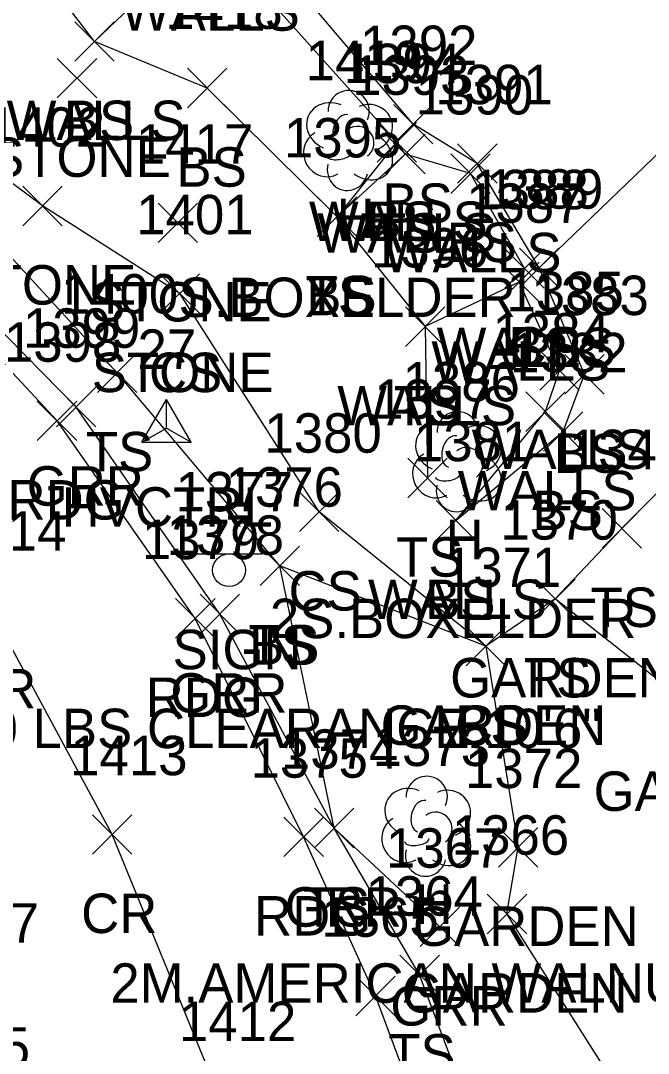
# Model space of a CAD drawing. Extents: x 1459992 to 1461532, y 647785 to 648535.
# Drawn here: x 1461373.7 to 1461405.5, y 648118.2 to 648170.5 of the extents above; entities that cross this region are included whole.
import ezdxf

# ---------------------------------------------------------------- set-up
doc = ezdxf.new("R2010")
doc.units = 0
for name, color, linetype in [('C_A', 7, 'Continuous'), ('C_I', 7, 'Continuous'), ('CPSM', 7, 'Continuous'), ('L_A', 7, 'Continuous'), ('L_C', 7, 'Continuous'), ('L_I', 7, 'Continuous'), ('L_TIC', 7, 'Continuous'), ('LAPB', 7, 'Continuous'), ('LASF', 7, 'Continuous'), ('LELB', 7, 'Continuous'), ('LTD', 7, 'Continuous'), ('LWS', 7, 'Continuous'), ('P_A', 7, 'Continuous'), ('P_I', 7, 'Continuous'), ('P_TIC', 7, 'Continuous'), ('PEU', 7, 'Continuous'), ('PRC', 7, 'Continuous'), ('R_A', 7, 'Continuous'), ('R_I', 7, 'Continuous'), ('R_TIC', 7, 'Continuous'), ('RGR', 7, 'Continuous'), ('S_A', 7, 'Continuous'), ('S_C', 7, 'Continuous'), ('S_I', 7, 'Continuous'), ('SSGN', 7, 'Continuous')]:
    doc.layers.add(name, color=color, linetype=linetype)

msp = doc.modelspace()

# ---------------------------------------------------------------- linework, layer by layer
at = {"layer": 'CPSM'}
for p, q in [((1461379.852, 648149.141), (1461381.102, 648151.306)), ((1461382.352, 648149.141), (1461381.102, 648151.306)), ((1461381.102, 648149.863), (1461381.102, 648151.306)), ((1461379.852, 648149.141), (1461381.102, 648149.863)), ((1461381.102, 648149.863), (1461381.102, 648149.863)), ((1461381.102, 648149.863), (1461382.352, 648149.141)), ((1461379.852, 648149.141), (1461382.352, 648149.141))]:
    msp.add_line(p, q, dxfattribs=at)
at = {"layer": 'L_TIC'}
for points in [[(1461376.464, 648168.459), (1461378.464, 648170.459)], [(1461378.464, 648168.459), (1461376.464, 648170.459)], [(1461376.464, 648168.459), (1461378.464, 648170.459)], [(1461378.464, 648168.459), (1461376.464, 648170.459)], [(1461375.571, 648166.594), (1461377.571, 648168.594)], [(1461377.571, 648166.594), (1461375.571, 648168.594)], [(1461382.172, 648166.096), (1461384.172, 648168.096)], [(1461384.172, 648166.096), (1461382.172, 648168.096)], [(1461392.612, 648164.262), (1461394.612, 648166.262)], [(1461394.612, 648164.262), (1461392.612, 648166.262)], [(1461391.781, 648163.345), (1461393.781, 648165.345)], [(1461393.781, 648163.345), (1461391.781, 648165.345)], [(1461391.781, 648163.345), (1461393.781, 648165.345)], [(1461393.781, 648163.345), (1461391.781, 648165.345)], [(1461392.211, 648162.751), (1461394.211, 648164.751)], [(1461394.211, 648162.751), (1461392.211, 648164.751)], [(1461392.211, 648162.751), (1461394.211, 648164.751)], [(1461394.211, 648162.751), (1461392.211, 648164.751)], [(1461395.519, 648161.757), (1461397.519, 648163.757)], [(1461397.519, 648161.757), (1461395.519, 648163.757)], [(1461395.861, 648162.276), (1461397.861, 648164.276)], [(1461397.861, 648162.276), (1461395.861, 648164.276)], [(1461373.821, 648160.121), (1461375.821, 648162.121)], [(1461375.821, 648160.121), (1461373.821, 648162.121)], [(1461380.683, 648159.265), (1461382.683, 648161.265)], [(1461382.683, 648159.265), (1461380.683, 648161.265)], [(1461388.751, 648159.577), (1461390.751, 648161.577)], [(1461390.751, 648159.577), (1461388.751, 648161.577)], [(1461388.751, 648159.577), (1461390.751, 648161.577)], [(1461390.751, 648159.577), (1461388.751, 648161.577)], [(1461398.256, 648156.952), (1461400.256, 648158.952)], [(1461400.256, 648156.952), (1461398.256, 648158.952)], [(1461399, 648156.981), (1461401, 648158.981)], [(1461401, 648156.981), (1461399, 648158.981)], [(1461399, 648156.981), (1461401, 648158.981)], [(1461401, 648156.981), (1461399, 648158.981)], [(1461397.988, 648156.264), (1461399.988, 648158.264)], [(1461399.988, 648156.264), (1461397.988, 648158.264)], [(1461397.988, 648156.264), (1461399.988, 648158.264)], [(1461399.988, 648156.264), (1461397.988, 648158.264)], [(1461380.779, 648155.684), (1461382.779, 648157.684)], [(1461382.779, 648155.684), (1461380.779, 648157.684)], [(1461380.779, 648155.684), (1461382.779, 648157.684)], [(1461382.779, 648155.684), (1461380.779, 648157.684)], [(1461380.779, 648155.684), (1461382.779, 648157.684)], [(1461382.779, 648155.684), (1461380.779, 648157.684)], [(1461393.218, 648154.003), (1461395.218, 648156.003)], [(1461395.218, 648154.003), (1461393.218, 648156.003)], [(1461393.218, 648154.003), (1461395.218, 648156.003)], [(1461395.218, 648154.003), (1461393.218, 648156.003)], [(1461377.611, 648151.668), (1461379.611, 648153.668)], [(1461379.611, 648151.668), (1461377.611, 648153.668)], [(1461400.031, 648151.786), (1461402.031, 648153.786)], [(1461402.031, 648151.786), (1461400.031, 648153.786)], [(1461401.296, 648151.589), (1461403.296, 648153.589)], [(1461403.296, 648151.589), (1461401.296, 648153.589)], [(1461399.322, 648149.694), (1461401.322, 648151.694)], [(1461401.322, 648149.694), (1461399.322, 648151.694)], [(1461400.217, 648148.693), (1461402.217, 648150.693)], [(1461402.217, 648148.693), (1461400.217, 648150.693)], [(1461393.334, 648146.331), (1461395.334, 648148.331)], [(1461395.334, 648146.331), (1461393.334, 648148.331)], [(1461387.851, 648144.613), (1461389.851, 648146.613)], [(1461389.851, 648144.613), (1461387.851, 648146.613)], [(1461394.776, 648144.183), (1461396.776, 648146.183)], [(1461396.776, 648144.183), (1461394.776, 648146.183)], [(1461394.776, 648144.183), (1461396.776, 648146.183)], [(1461396.776, 648144.183), (1461394.776, 648146.183)], [(1461403.189, 648143.779), (1461405.189, 648145.779)], [(1461405.189, 648143.779), (1461403.189, 648145.779)], [(1461385.85, 648141.876), (1461387.85, 648143.876)], [(1461387.85, 648141.876), (1461385.85, 648143.876)], [(1461385.85, 648141.876), (1461387.85, 648143.876)], [(1461387.85, 648141.876), (1461385.85, 648143.876)], [(1461399.813, 648140.208), (1461401.813, 648142.208)], [(1461401.813, 648140.208), (1461399.813, 648142.208)], [(1461399.813, 648140.208), (1461401.813, 648142.208)], [(1461401.813, 648140.208), (1461399.813, 648142.208)], [(1461396.294, 648137.804), (1461398.294, 648139.804)], [(1461398.294, 648137.804), (1461396.294, 648139.804)], [(1461396.294, 648137.804), (1461398.294, 648139.804)], [(1461398.294, 648137.804), (1461396.294, 648139.804)], [(1461396.294, 648137.804), (1461398.294, 648139.804)], [(1461398.294, 648137.804), (1461396.294, 648139.804)], [(1461388.604, 648128.591), (1461390.604, 648130.591)], [(1461390.604, 648128.591), (1461388.604, 648130.591)], [(1461397.931, 648127.614), (1461399.931, 648129.614)], [(1461399.931, 648127.614), (1461397.931, 648129.614)], [(1461397.931, 648127.614), (1461399.931, 648129.614)], [(1461399.931, 648127.614), (1461397.931, 648129.614)], [(1461397.363, 648124.235), (1461399.363, 648126.235)], [(1461399.363, 648124.235), (1461397.363, 648126.235)], [(1461392.938, 648121.147), (1461394.938, 648123.147)], [(1461394.938, 648121.147), (1461392.938, 648123.147)]]:
    msp.add_lwpolyline(points, dxfattribs=at)
at = {"layer": 'LAPB'}
for points in [[(1461407.924, 648110.162), (1461411.912, 648123.815), (1461408.084, 648135.457), (1461400.813, 648141.208), (1461397.294, 648138.804), (1461398.931, 648128.614)], [(1461407.924, 648110.162), (1461398.363, 648125.235), (1461398.931, 648128.614)]]:
    msp.add_lwpolyline(points, dxfattribs=at)
at = {"layer": 'LASF'}
msp.add_lwpolyline([(1461381.779, 648156.684), (1461374.821, 648161.121), (1461367.27, 648166.741), (1461364.684, 648166.619), (1461366.684, 648167.245)], dxfattribs=at)
at = {"layer": 'LELB'}
for points in [[(1461400, 648157.981), (1461410.206, 648167.796), (1461433.497, 648170.261), (1461450.015, 648174.465), (1461460.23, 648178.212), (1461481.957, 648192.378), (1461506.16, 648200.217)], [(1461395.776, 648145.183), (1461401.217, 648149.693), (1461402.296, 648152.589), (1461400, 648157.981), (1461396.861, 648163.276), (1461393.612, 648165.262), (1461384.114, 648176.457), (1461379.778, 648178.815), (1461366.22, 648181.937)], [(1461392.781, 648164.345), (1461389.751, 648160.577), (1461383.172, 648167.096), (1461377.464, 648169.459), (1461372.614, 648175.782)], [(1461437.839, 648100.682), (1461424.99, 648102.601), (1461410.253, 648104.75), (1461403.249, 648108.099), (1461397.824, 648111.829), (1461393.938, 648122.147), (1461389.604, 648129.591), (1461386.85, 648142.876), (1461378.611, 648152.668), (1461368.623, 648163.532), (1461366.902, 648163.443), (1461362.607, 648163.899), (1461362.17, 648163.299)], [(1461393.211, 648163.751), (1461389.751, 648160.577), (1461394.218, 648155.003), (1461394.334, 648147.331)], [(1461397.294, 648138.804), (1461388.851, 648145.613), (1461381.779, 648156.684)], [(1461411.698, 648152.367), (1461404.189, 648144.779), (1461400.813, 648141.208)], [(1461397.294, 648138.804), (1461386.85, 648142.876)]]:
    msp.add_lwpolyline(points, dxfattribs=at)
at = {"layer": 'LTD'}
for p, q in [((1461390.294, 648164.49), (1461390.294, 648164.49)), ((1461390.294, 648164.49), (1461390.294, 648164.49)), ((1461395.818, 648148.214), (1461395.818, 648148.214)), ((1461395.818, 648148.214), (1461395.818, 648148.214)), ((1461394.253, 648129.733), (1461394.253, 648129.733)), ((1461394.253, 648129.733), (1461394.253, 648129.733))]:
    msp.add_line(p, q, dxfattribs=at)
for centre in [(1461390.341, 648165.924), (1461395.865, 648149.648), (1461394.3, 648131.167)]:
    msp.add_arc(centre, 1.047, 335.5272, 180.9563, dxfattribs=at)
for centre, major_axis, ratio, start_param, end_param in [((1461389.502, 648165.157), (1.21, -0.512), 0.895232, 1.570796, 4.712389), ((1461391.335, 648165.074), (-1.141, -0.483), 0.949671, 1.570796, 4.712389), ((1461390.085, 648164.948), (-0.208, -0.792), 0.645439, 3.141593, 6.283185), ((1461389.211, 648163.782), (0.584, -1.042), 0.959034, 3.141593, 6.283185), ((1461390.794, 648164.323), (-0.5, 0.667), 0.989748, 3.141593, 6.283185), ((1461391.294, 648163.657), (-1.09, 0.792), 0.841452, 1.570796, 4.712389), ((1461389.836, 648163.74), (-0.625, -0.083), 0.423636, 0, 3.141593), ((1461390.294, 648162.99), (0.265, 1.061), 0.942809, 1.570796, 4.712389), ((1461395.026, 648148.881), (1.21, -0.512), 0.895232, 1.570796, 4.712389), ((1461396.86, 648148.798), (-1.141, -0.483), 0.949671, 1.570796, 4.712389), ((1461395.61, 648148.673), (-0.208, -0.792), 0.645439, 3.141593, 6.283185), ((1461396.318, 648148.048), (-0.5, 0.667), 0.989748, 3.141593, 6.283185), ((1461394.735, 648147.506), (0.584, -1.042), 0.959034, 3.141593, 6.283185), ((1461396.818, 648147.381), (-1.09, 0.792), 0.841452, 1.570796, 4.712389), ((1461395.36, 648147.464), (-0.625, -0.083), 0.423636, 0, 3.141593), ((1461395.818, 648146.714), (0.265, 1.061), 0.942809, 1.570796, 4.712389), ((1461393.461, 648130.399), (1.21, -0.512), 0.895232, 1.570796, 4.712389), ((1461395.294, 648130.316), (-1.141, -0.483), 0.949671, 1.570796, 4.712389), ((1461394.044, 648130.191), (-0.208, -0.792), 0.645439, 3.141593, 6.283185), ((1461394.753, 648129.566), (-0.5, 0.667), 0.989748, 3.141593, 6.283185), ((1461393.17, 648129.024), (0.584, -1.042), 0.959034, 3.141593, 6.283185), ((1461395.253, 648128.9), (-1.09, 0.792), 0.841452, 1.570796, 4.712389), ((1461393.795, 648128.983), (-0.625, -0.083), 0.423636, 0, 3.141593), ((1461394.253, 648128.233), (0.265, 1.061), 0.942809, 1.570796, 4.712389)]:
    msp.add_ellipse(centre, major_axis=major_axis, ratio=ratio, start_param=start_param, end_param=end_param, dxfattribs=at)
at = {"layer": 'LWS'}
for points in [[(1461395.776, 648145.183), (1461400.322, 648150.694), (1461401.031, 648152.786), (1461398.988, 648157.264), (1461399.256, 648157.952), (1461396.519, 648162.757), (1461393.211, 648163.751), (1461392.781, 648164.345), (1461383.255, 648175.001), (1461379.666, 648178.519), (1461366.22, 648181.937), (1461358.31, 648179.355), (1461359.375, 648177.485)], [(1461383.255, 648175.001), (1461377.464, 648169.459)], [(1461398.988, 648157.264), (1461394.218, 648155.003)]]:
    msp.add_lwpolyline(points, dxfattribs=at)
at = {"layer": 'P_TIC'}
for points in [[(1461374.562, 648149.224), (1461376.562, 648151.224)], [(1461376.562, 648149.224), (1461374.562, 648151.224)], [(1461381.567, 648139.218), (1461383.567, 648141.218)], [(1461383.567, 648139.218), (1461381.567, 648141.218)], [(1461377.351, 648128.267), (1461379.351, 648130.267)], [(1461379.351, 648128.267), (1461377.351, 648130.267)], [(1461387.059, 648128.141), (1461389.059, 648130.141)], [(1461389.059, 648128.141), (1461387.059, 648130.141)], [(1461390.697, 648120.078), (1461392.697, 648122.078)], [(1461392.697, 648120.078), (1461390.697, 648122.078)]]:
    msp.add_lwpolyline(points, dxfattribs=at)
at = {"layer": 'PEU'}
msp.add_lwpolyline([(1461405.272, 648031.274), (1461404.297, 648042.515), (1461403.915, 648074), (1461402.282, 648079.787), (1461395.979, 648109.613), (1461391.697, 648121.078), (1461388.059, 648129.141), (1461382.567, 648140.218), (1461375.562, 648150.224), (1461367.209, 648159.2), (1461362.17, 648163.299), (1461358.126, 648158.61), (1461353.744, 648153.756)], dxfattribs=at)
at = {"layer": 'PRC'}
msp.add_lwpolyline([(1461399.102, 647801.607), (1461400.203, 647838.194), (1461399.73, 647875.765), (1461399.539, 647898.401), (1461398.446, 647928.211), (1461395.012, 647961.974), (1461394.123, 647993.813), (1461392.15, 648024.041), (1461390.381, 648057.367), (1461388.518, 648080.662), (1461387.016, 648100.033), (1461383.866, 648115.79), (1461378.351, 648129.267), (1461372.213, 648140.65), (1461365.441, 648150.969), (1461358.126, 648158.61)], dxfattribs=at)
at = {"layer": 'R_TIC'}
for points in [[(1461375.533, 648149.93), (1461377.533, 648151.93)], [(1461377.533, 648149.93), (1461375.533, 648151.93)], [(1461382.809, 648139.436), (1461384.809, 648141.436)], [(1461384.809, 648139.436), (1461382.809, 648141.436)], [(1461388.604, 648128.591), (1461390.604, 648130.591)], [(1461390.604, 648128.591), (1461388.604, 648130.591)], [(1461393.966, 648123.578), (1461395.966, 648125.578)], [(1461395.966, 648123.578), (1461393.966, 648125.578)]]:
    msp.add_lwpolyline(points, dxfattribs=at)
at = {"layer": 'RGR'}
msp.add_lwpolyline([(1461394.966, 648124.578), (1461389.604, 648129.591), (1461383.809, 648140.436), (1461376.533, 648150.93), (1461367.825, 648159.773), (1461362.607, 648163.899)], dxfattribs=at)
at = {"layer": 'SSGN'}
for p, q in [((1461382.631, 648143.493), (1461385.964, 648143.493)), ((1461384.278, 648142.659), (1461384.278, 648142.659))]:
    msp.add_line(p, q, dxfattribs=at)
msp.add_circle((1461384.278, 648142.659), 0.833, dxfattribs=at)

# ---------------------------------------------------------------- texts
at = {"layer": 'C_A'}
msp.add_text('HVCTRL', height=2, dxfattribs=at).set_placement((1461375.795, 648144.863))
at = {"layer": 'C_I'}
msp.add_text('27', height=2, dxfattribs=at).set_placement((1461379.638, 648152.863))
at = {"layer": 'L_A'}
for s, p in [('WALLS', (1461378.798, 648170.001)), ('WALLS', (1461378.798, 648170.001)), ('WALLS', (1461373.007, 648164.459)), ('BS', (1461375.905, 648164.459)), ('STONE', (1461372.114, 648162.594)), ('BS', (1461381.612, 648162.096)), ('BS', (1461392.053, 648160.262)), ('WALLS', (1461388.324, 648159.345)), ('H', (1461389.727, 648159.49)), ('BS', (1461391.222, 648159.345)), ('WALLS', (1461388.754, 648158.751)), ('TS', (1461391.621, 648158.751)), ('BS', (1461395.302, 648158.276)), ('WALLS', (1461392.063, 648157.757)), ('STONE', (1461370.364, 648156.121)), ('TS', (1461388.161, 648155.577)), ('BS', (1461388.192, 648155.577)), ('STONE', (1461377.226, 648155.265)), ('WALLS', (1461394.8, 648152.952)), ('CS', (1461398.441, 648152.981)), ('BS', (1461398.441, 648152.981)), ('WALLS', (1461394.531, 648152.264)), ('WALLS', (1461394.531, 648152.264)), ('STONE', (1461377.322, 648151.684)), ('STONE', (1461377.322, 648151.684)), ('CS', (1461380.22, 648151.684)), ('WALLS', (1461389.761, 648150.003)), ('TS', (1461392.627, 648150.003)), ('TS', (1461377.02, 648147.668)), ('WALLS', (1461396.574, 648147.786)), ('BS', (1461400.736, 648147.589)), ('WALLS', (1461395.865, 648145.694)), ('BS', (1461399.658, 648144.693)), ('H', (1461395.251, 648143.214)), ('TS', (1461392.744, 648142.331)), ('CS', (1461387.292, 648140.613)), ('WALLS', (1461391.319, 648140.183)), ('BS', (1461394.217, 648140.183)), ('TS', (1461402.599, 648139.779)), ('TS', (1461385.259, 648137.876)), ('BS', (1461385.291, 648137.876)), ('GARDEN', (1461395.483, 648136.208)), ('TS', (1461399.223, 648136.208)), ('GARDEN', (1461391.963, 648133.804)), ('CS', (1461395.735, 648133.804)), ('BS', (1461395.735, 648133.804)), ('GARDEN', (1461402.754, 648130.457)), ('TS', (1461388.013, 648124.591)), ('H', (1461393.686, 648124.733)), ('GARDEN', (1461393.6, 648123.614)), ('GARDEN', (1461393.6, 648123.614)), ('GARDEN', (1461393.032, 648120.235)), ('TS', (1461392.347, 648117.147))]:
    msp.add_text(s, height=2, dxfattribs=at).set_placement(p)
at = {"layer": 'L_C'}
for s, p in [('S.BOXELDER', (1461381.719, 648155.49)), ('2S.BOXELDER', (1461386.346, 648139.214)), ('2M.AMERICAN WALNUT', (1461378.261, 648120.733))]:
    msp.add_text(s, height=2, dxfattribs=at).set_placement(p)
at = {"layer": 'L_I'}
for s, p in [('1418', (1461381.046, 648170.096)), ('1392', (1461390.919, 648168.262)), ('1419', (1461388.16, 648167.49)), ('1394', (1461390.088, 648167.345)), ('1394', (1461390.088, 648167.345)), ('1393', (1461390.518, 648166.751)), ('1393', (1461390.518, 648166.751)), ('1391', (1461394.735, 648166.276)), ('1390', (1461393.74, 648165.757)), ('1402', (1461372.049, 648164.121)), ('1395', (1461387.058, 648163.577)), ('1395', (1461387.058, 648163.577)), ('1417', (1461379.557, 648163.265)), ('1388', (1461396.564, 648160.952)), ('1389', (1461397.299, 648160.981)), ('1389', (1461397.299, 648160.981)), ('1387', (1461396.295, 648160.264)), ('1387', (1461396.295, 648160.264)), ('1401', (1461379.574, 648159.684)), ('1401', (1461379.574, 648159.684)), ('1401', (1461379.574, 648159.684)), ('1396', (1461391.47, 648158.003)), ('1396', (1461391.47, 648158.003)), ('1400', (1461375.753, 648155.668)), ('1385', (1461398.338, 648155.786)), ('1383', (1461399.603, 648155.589)), ('1384', (1461397.629, 648153.694)), ('1382', (1461398.524, 648152.693)), ('1386', (1461393.07, 648151.214)), ('1397', (1461391.641, 648150.331)), ('1380', (1461386.071, 648148.613)), ('1381', (1461393.65, 648148.183)), ('1381', (1461393.65, 648148.183)), ('1348', (1461401.496, 648147.779)), ('1376', (1461384.102, 648145.876)), ('1376', (1461384.102, 648145.876)), ('1370', (1461398.034, 648144.208)), ('1370', (1461398.034, 648144.208)), ('1371', (1461395.168, 648141.804)), ('1371', (1461395.168, 648141.804)), ('1371', (1461395.168, 648141.804)), ('1374', (1461386.911, 648132.591)), ('1373', (1461391.56, 648132.733)), ('1372', (1461396.238, 648131.614)), ('1372', (1461396.238, 648131.614)), ('1366', (1461395.568, 648128.235)), ('1364', (1461391.198, 648125.147))]:
    msp.add_text(s, height=2, dxfattribs=at).set_placement(p)
at = {"layer": 'P_A'}
for s, p in [('RDG', (1461373.05, 648145.224)), ('CR', (1461370.646, 648135.65)), ('RDG', (1461380.055, 648135.218)), ('CR', (1461376.784, 648124.267)), ('RDG', (1461385.547, 648124.141))]:
    msp.add_text(s, height=2, dxfattribs=at).set_placement(p)
at = {"layer": 'P_I'}
for s, p in [('1398', (1461372.869, 648153.224)), ('1414', (1461370.087, 648143.65)), ('1379', (1461379.866, 648143.218)), ('1413', (1461376.225, 648132.267)), ('1375', (1461385.366, 648132.141)), ('1365', (1461388.957, 648124.078)), ('1477', (1461368.696, 648123.78)), ('1412', (1461381.74, 648118.79))]:
    msp.add_text(s, height=2, dxfattribs=at).set_placement(p)
at = {"layer": 'R_A'}
for p in [(1461374.021, 648145.93), (1461381.297, 648135.436), (1461387.092, 648124.591), (1461392.454, 648119.578)]:
    msp.add_text('GRR', height=2, dxfattribs=at).set_placement(p)
at = {"layer": 'R_I'}
for s, p in [('1399', (1461373.832, 648153.93)), ('1378', (1461381.116, 648143.436)), ('1374', (1461386.911, 648132.591)), ('1367', (1461392.226, 648127.578)), ('1475', (1461368.246, 648117.496))]:
    msp.add_text(s, height=2, dxfattribs=at).set_placement(p)
at = {"layer": 'S_A'}
msp.add_text('SIGN', height=2, dxfattribs=at).set_placement((1461381.416, 648137.639))
at = {"layer": 'S_C'}
msp.add_text('MWL 10000 LBS CLEARANCE 10\'6"', height=2, dxfattribs=at).set_placement((1461359.156, 648133.639))
at = {"layer": 'S_I'}
msp.add_text('1377', height=2, dxfattribs=at).set_placement((1461381.565, 648145.639))

doc.saveas('drawing.dxf')
